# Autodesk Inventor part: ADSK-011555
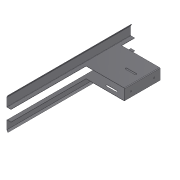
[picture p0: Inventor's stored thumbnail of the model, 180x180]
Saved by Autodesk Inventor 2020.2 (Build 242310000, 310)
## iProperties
Created: 2000-02
Part Number: ADSK-011555
Material: 1.0312 DC05
Description: FSHTPH,SS,CP,00,097,073,280,STOP,ADJ
Document SubType Name: Tôlerie
Designer: cmcgourin
Density: 1 g/cm^3
Sheet Metal Rule: Stahlblech 1.0312 - DC05 -   1.5mm
Appearance: Metal-Steel(Polish)
Mass: 330.292 g
Surface Area: 4467.85 cm^2
Volume: 330.292 cm^3
Flat Pattern Width: 71.1 cm
Flat Pattern Length: 67.2018 cm
Flat Pattern Area: 4778.05 cm^2
Sheet Metal Width: 711,000 mm
Sheet Metal Length: 672,018 mm
Sheet Metal Area: 477804,966 mm^2
Control State: 0
Checked Out: False
Master: False
Shininess: 0.0
Length Units: 11269
Angle Units: 11279
Time Units: 11290
Mass Units: 11283
Length Display Precision: 3
Angle Display Precision: 2
Compacted: True
Cutlength: 745 SI (26.60 X 28.00)
Material_Number: A084639
Material Desc: SHEET,SS,16 GA
G_L: 711x672 mm
Thickness: 1,500 mm
Dimensions: 184x711x246,5 mm
Mass: 0,33 kg
Semi finished: Stahlblech 1.0312 - DC05 -   1.5mm
VLT_Material: 1.0312 DC05
Density: 0.0
Volumn: 0.0
Area: 0.0
PropertySet Name: Model Information
Title: 500595R
Author: cmcgourin
Revision Number: -
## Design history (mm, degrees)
sketch "Skizze6"
  geometry: L1 (-167.5, 29.5)-(-35.5, 29.5); L2 (-203, 59)-(-203, 0) reference; L3 (0, 59)-(-203, 59) reference; 6 further points
  constraints: 3 midpoint, 2 coincident, 2 end point, 1 horizontal, 1 horizontal alignment, 1 vertical alignment
  dimensions: "d67" = 132 distance of L1.start L1.end
hole "Bohrung1" sketch "Skizze6" diameter "d68" = 9; stored, may be unused: countersink angle "d72" = 90 deg, drill point angle "d74" = 118 deg; dims "d69" = 6, "d70" = 15, "d71" = 9, "d73" = 1.5 (= Thickness)
workplane "Arbeitsebene1"
workplane "Arbeitsebene2"
workplane "Arbeitsebene3"
sketch "Sketch4"
  geometry: L1 (93.656, -20.45)-(148.656, -20.45); L2 (148.656, -20.45)-(148.656, -30.45); L3 (148.656, -30.45)-(93.656, -30.45); L4 (93.656, -30.45)-(93.656, -20.45); L5 (93.656, -172.95)-(148.656, -172.95); L6 (148.656, -182.95)-(93.656, -182.95); L7 (148.656, -177.95)-(93.656, -177.95); L8 (148.656, -25.45)-(93.656, -25.45); L9 (121.156, -177.95)-(121.156, -25.45); L10 (221.156, -203.2)-(221.156, -0.2) reference; A1 r 5 centre (93.656, -25.45) between (93.656, -20.45) and (93.656, -30.45); A2 r 5 centre (148.656, -25.45) between (148.656, -30.45) and (148.656, -20.45); A3 r 5 centre (93.656, -177.95) between (93.656, -172.95) and (93.656, -182.95); A4 r 5 centre (148.656, -177.95) between (148.656, -182.95) and (148.656, -172.95); 2 further points
  constraints: 18 end point, 8 point on circle, 8 tangent, 6 midpoint, 4 centre point, 4 point on line, 3 horizontal, 3 parallel, 2 equal radius, 2 perpendicular, 1 horizontal alignment
  dimensions: "d25" = 10 distance between parallel lines of L1 L3 (= d31); "d27" = 55 distance between parallel lines of L2 L4 (= d34); "d31" = 10 distance between parallel lines of L5 L6; "d34" = 55 distance of L7.start L7.end; "d59" = 152.5 distance of L9.start L9.end; "d60" = 100 distance between parallel lines of L10 L9
feature "Ausklinkung1" sketch "Sketch4" dims "d61" = 1.5 (= Thickness), "d62" = 0
feature "Grobblech1" dims "d47" = 1.5 (= Thickness), "d48" = 1.5 (= BendReliefWidth), "d49" = 0.75 (= BendReliefDepth), "d50" = 3 (= MinimumRemnant), "d51" = 1.5 (= TransitionRadius), "d52" = 711, "d53" = 1.5 (= BendRadius), "d54" = 1.5, "d55" = 6 (= CornerReliefSize), "d56" = 1.5 (= TailleJeu), "d57" = 1.5 (= TailleRayonJacobi), "SeamGap" = 0.00508
feature "Biegung1" dims "d47" = 1.5 (= Thickness), "d48" = 1.5 (= BendReliefWidth), "d49" = 0.75 (= BendReliefDepth), "d50" = 3 (= MinimumRemnant), "d51" = 1.5 (= TransitionRadius), "d53" = 1.5 (= BendRadius), "d54" = 1.5, "SeamGap" = 0.00508
node "Konturlasche1"
  sketch "Sketch1"
    geometry: L1 (-245, -81)-(-245, -31); L2 (-245, -31)-(0, -31); L3 (0, -31)-(0, 31); L4 (0, 31)-(-245, 31); L5 (-245, 31)-(-245, 81); L6 (-245, 81)-(-238.65, 91.999); L7 (-245, -81)-(-238.65, -91.999); 2 further points
    constraints: 14 end point, 2 collinear, 2 parallel, 1 coincident, 1 equal length, 1 horizontal, 1 midpoint, 1 perpendicular
    dimensions: "d1" = 50 distance of L4.end L5.end; "d2" = 50 distance of L1.start L1.end (= d1); "d4" = 62 distance between parallel lines of L4 L2; "d7" = 12.7 distance of L5.end L6.end; "d8" = 30 deg angle of L7 L1; "d64" = 245 distance between parallel lines of L3 L5; "d65" = 30 deg angle of L6 L5 (= d8); "d66" = 12.7 distance of L1.start L7.end (derived)
feature "Ecke1" dims "d54" = 1.5, "d55" = 6 (= CornerReliefSize), "d56" = 1.5 (= TailleJeu), "d57" = 1.5 (= TailleRayonJacobi)
node "Extrusion2" dims "d17" = 609.6, "d18" = 0
  sketch "Sketch3"
    geometry: L1 (246.013, 0)-(24.013, 0); L2 (24.013, 0)-(24.013, 432); L3 (24.013, 432)-(246.013, 432); L4 (246.013, 432)-(246.013, 0); L5 (246.013, 711)-(24.013, 711); L6 (24.013, 711)-(24.013, 635); L7 (24.013, 635)-(246.013, 635); L8 (246.013, 635)-(246.013, 711); L9 (2.513, 711)-(243.013, 711) reference; L10 (2.513, 0)-(243.013, 0) reference; L11 (246.013, 711)-(246.013, 0) reference
    constraints: 16 end point, 5 collinear, 4 parallel, 2 horizontal, 2 perpendicular
    dimensions: "d14" = 432 distance of L1.end L2.end; "d15" = 76 distance of L5.end L6.end; "d58" = 222 distance between parallel lines of L4 L2
sketch "Sketch5"
  geometry: L1 (128.303, 538.5)-(183.303, 538.5); L2 (183.303, 528.5)-(128.303, 528.5); L3 (221.303, 635)-(221.303, 432) reference; A1 r 5 centre (128.303, 533.5) between (128.303, 538.5) and (128.303, 528.5); A2 r 5 centre (183.303, 533.5) between (183.303, 528.5) and (183.303, 538.5); 1 further point
  constraints: 4 end point, 4 point on circle, 4 tangent, 2 centre point, 1 equal radius, 1 horizontal, 1 horizontal alignment, 1 midpoint, 1 parallel
  dimensions: "d39" = 10 distance between parallel lines of L1 L2; "d44" = 55 distance of A2.centre A1.centre; "d63" = 38 distance from line of L3 A2.centre
node "Extrusion4" dims "d45" = 25.4, "d46" = 0
node "Solide1"
node "Corps solides"
node "Corps surfaciques"
feature "Definition1"
feature "쀀䁏"
other parameters: "Thickness" = 1.5 (derived), "BendRadius" = 1.5 (= Thickness), "BendReliefWidth" = 1.5 (= Thickness), "BendReliefDepth" = 0.75 (= 0.5 x Thickness), "CornerReliefSize" = 6 (= 4 x Thickness), "MinimumRemnant" = 3 (= 2 x Thickness), "TransitionRadius" = 1.5 (= BendRadius), "TailleRayonJacobi" = 1.5 (= BendRadius), "TailleJeu" = 1.5 (= Thickness), "BendRadius" = 1.5, "BendReliefDepth" = 0.75, "BendReliefWidth" = 1.5, "CornerReliefSize" = 6, "MinimumRemnant" = 3, "TailleJeu" = 1.5, "TailleRayonJacobi" = 1.5, "Thickness" = 1.5, "TransitionRadius" = 1.5
